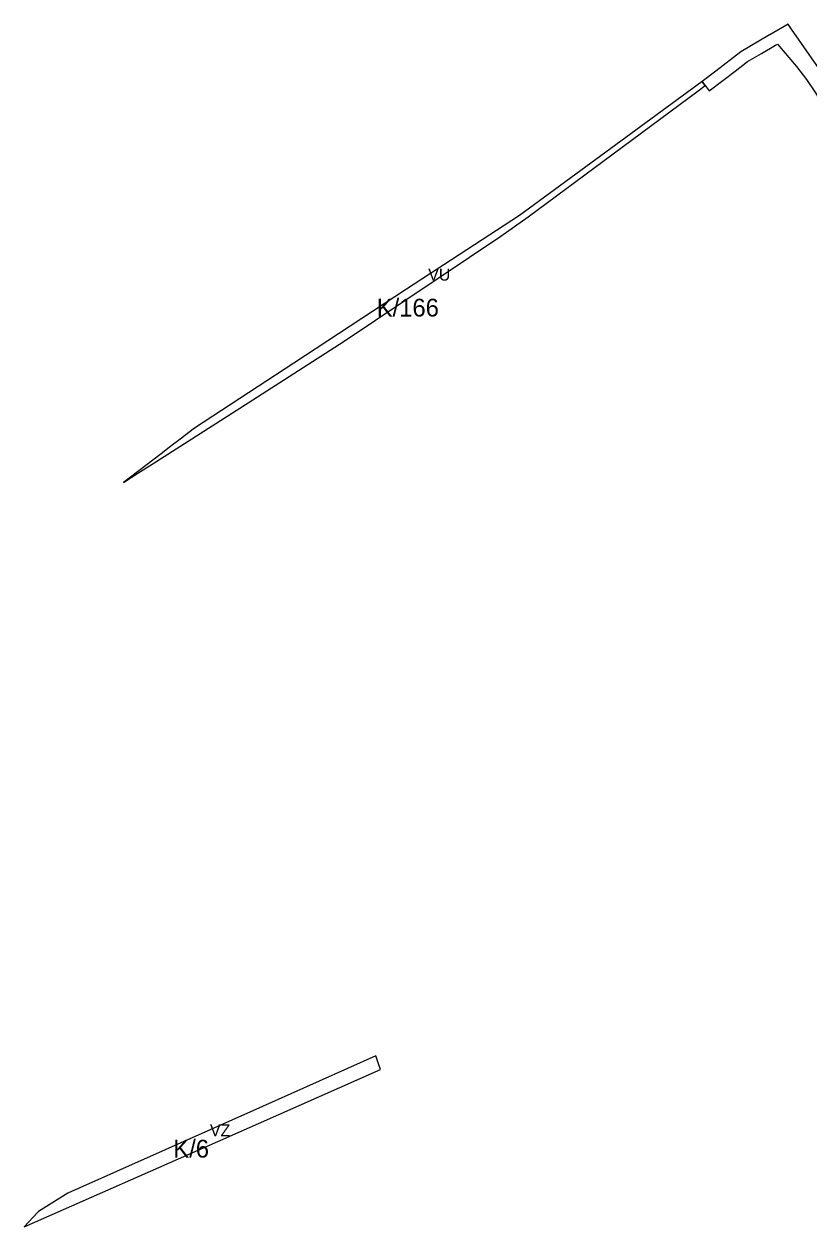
# Model space of a CAD drawing. Extents: x -521939 to -518034, y -1194984 to -1189555.
# Drawn here: x -521548 to -520886, y -1190759 to -1189744 of the extents above; entities that cross this region are included whole.
import ezdxf

# ---------------------------------------------------------------- set-up
doc = ezdxf.new("R2010")
doc.units = 0
for name, color, linetype in [('95420023', 7, 'Continuous'), ('96111023', 7, 'Continuous'), ('96141023', 7, 'Continuous'), ('96202223', 7, 'Continuous')]:
    doc.layers.add(name, color=color, linetype=linetype)

msp = doc.modelspace()

# ---------------------------------------------------------------- linework, layer by layer
at = {"layer": '95420023'}
for points in [[(-520903.31, -1189744.33), (-520918.65, -1189753.34), (-520918.93, -1189753.5)], [(-520900.54, -1189748.5), (-520903.31, -1189744.33)], [(-520868.84, -1189794.27), (-520900.54, -1189748.5)], [(-520971.53, -1189798.42), (-520969.8, -1189800.72), (-520958.26, -1189791.88), (-520947.93, -1189783.96), (-520937.6, -1189776.04), (-520925.76, -1189769.09), (-520913.92, -1189762.15), (-520912.37, -1189761.25)], [(-520918.93, -1189753.5), (-520943.19, -1189767.73)], [(-520912.37, -1189761.25), (-520896.35, -1189780.16)], [(-520943.19, -1189767.73), (-520964.34, -1189783.94)], [(-520896.35, -1189780.16), (-520887.88, -1189790.95), (-520880.21, -1189802.32), (-520872.55, -1189815.19), (-520859.28, -1189843.65), (-520825.3, -1189922.44), (-520803.36, -1189980.65), (-520787.67, -1190041.34), (-520778.83, -1190102.4), (-520777.95, -1190124.57)], [(-520964.34, -1189783.94), (-520975.8, -1189792.72)], [(-520975.8, -1189792.72), (-520974.53, -1189794.42), (-520973.26, -1189796.11)], [(-520973.26, -1189796.11), (-520971.53, -1189798.42)]]:
    msp.add_lwpolyline(points, dxfattribs=at)
at = {"layer": '96111023'}
for points in [[(-520974.53, -1189794.42), (-520975.8, -1189792.72), (-521129.95, -1189905.7), (-521225, -1189967.98), (-521320.06, -1190030.25), (-521403.82, -1190085.13), (-521419.72, -1190097.27), (-521421.67, -1190098.76), (-521425.29, -1190101.52), (-521432.08, -1190106.71), (-521463.67, -1190130.83), (-521451.59, -1190123.19), (-521439.5, -1190115.54), (-521358.54, -1190063.68)], [(-521122.58, -1189906.88), (-520979.19, -1189800.51)], [(-520979.19, -1189800.51), (-520973.26, -1189796.11)], [(-520973.26, -1189796.11), (-520974.53, -1189794.42)], [(-521145.53, -1189923.09), (-521122.58, -1189906.88)], [(-521277.58, -1190011.81), (-521145.53, -1189923.09)], [(-521358.54, -1190063.68), (-521277.58, -1190011.81)], [(-521251.04, -1190614.64), (-521346.43, -1190657.14), (-521510.56, -1190730.26)], [(-521249.05, -1190620.36), (-521251.04, -1190614.64)], [(-521247.06, -1190626.08), (-521249.05, -1190620.36)], [(-521384.14, -1190686.63), (-521247.06, -1190626.08)], [(-521547.56, -1190758.81), (-521384.14, -1190686.63)], [(-521510.56, -1190730.26), (-521535.38, -1190745.68)], [(-521535.38, -1190745.68), (-521536.01, -1190746.36), (-521547.56, -1190758.81)]]:
    msp.add_lwpolyline(points, dxfattribs=at)
at = {"layer": '96141023'}
for points in [[(-520975.8, -1189792.72), (-521129.95, -1189905.7), (-521225, -1189967.98), (-521320.06, -1190030.25), (-521403.82, -1190085.13), (-521419.72, -1190097.27), (-521421.67, -1190098.76), (-521425.29, -1190101.52)], [(-521122.58, -1189906.88), (-520979.19, -1189800.51)], [(-520979.19, -1189800.51), (-520973.26, -1189796.11)], [(-520974.53, -1189794.42), (-520975.8, -1189792.72)], [(-520973.26, -1189796.11), (-520974.53, -1189794.42)], [(-521145.53, -1189923.09), (-521122.58, -1189906.88)], [(-521358.54, -1190063.68), (-521277.58, -1190011.81), (-521145.53, -1189923.09)], [(-521439.5, -1190115.54), (-521358.54, -1190063.68)], [(-521432.08, -1190106.71), (-521463.67, -1190130.83), (-521451.59, -1190123.19)], [(-521425.29, -1190101.52), (-521432.08, -1190106.71)], [(-521451.59, -1190123.19), (-521439.5, -1190115.54)]]:
    msp.add_lwpolyline(points, dxfattribs=at)
at = {"layer": '96202223'}
for points in [[(-521251.04, -1190614.64), (-521346.43, -1190657.14), (-521510.56, -1190730.26)], [(-521249.05, -1190620.36), (-521251.04, -1190614.64)], [(-521247.06, -1190626.08), (-521249.05, -1190620.36)], [(-521384.14, -1190686.63), (-521247.06, -1190626.08)], [(-521547.56, -1190758.81), (-521384.14, -1190686.63)], [(-521510.56, -1190730.26), (-521535.38, -1190745.68)], [(-521535.38, -1190745.68), (-521536.01, -1190746.36), (-521547.56, -1190758.81)]]:
    msp.add_lwpolyline(points, dxfattribs=at)

# ---------------------------------------------------------------- texts
at = {"layer": '96111023'}
for s, rotation, p in [('K/166', 360, (-521250.2, -1189990.99)), ('K/6', 0, (-521421.71, -1190700.28))]:
    msp.add_text(s, height=15, rotation=rotation, dxfattribs=at).set_placement(p)
at = {"layer": '96141023'}
msp.add_text('VU', height=10, rotation=0, dxfattribs=at).set_placement((-521206.78, -1189960.73))
at = {"layer": '96202223'}
msp.add_text('VZ', height=10, rotation=0, dxfattribs=at).set_placement((-521390.77, -1190682.33))

doc.saveas('drawing.dxf')
